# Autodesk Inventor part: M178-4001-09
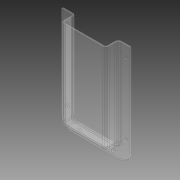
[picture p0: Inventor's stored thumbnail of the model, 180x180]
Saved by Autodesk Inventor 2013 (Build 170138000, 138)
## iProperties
Created: 2004-11
Part Number: M178-4001-09
Material: Plastic, Clear
Document SubType Name: Modeling
Designer: Autodesk, Inc.
Manufacturer: Standard
Standards Organization: Custom
Description: TOOL CADDY, PLASTIC, 2.5 x 5 x 1
Mass: 26.1813 g
Surface Area: 237.698 cm^2
Volume: 21.8178 cm^3
Density: 1.2 g/cm^3
CAGE: 1LJX3
Dept. ID: Product Design
Description #2: ---
Finish #1: ---
Finish #2: ---
Material ID: ---
Project Number: ---
Author: Autodesk, Inc.
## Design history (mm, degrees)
derived "M178-4001-XX.ipt"
body "Solid1"
tag "TaggingFeature2"
feature "Solid1::M178-4001-XX.ipt" dims "ScaleForDerivedMember" = 10
